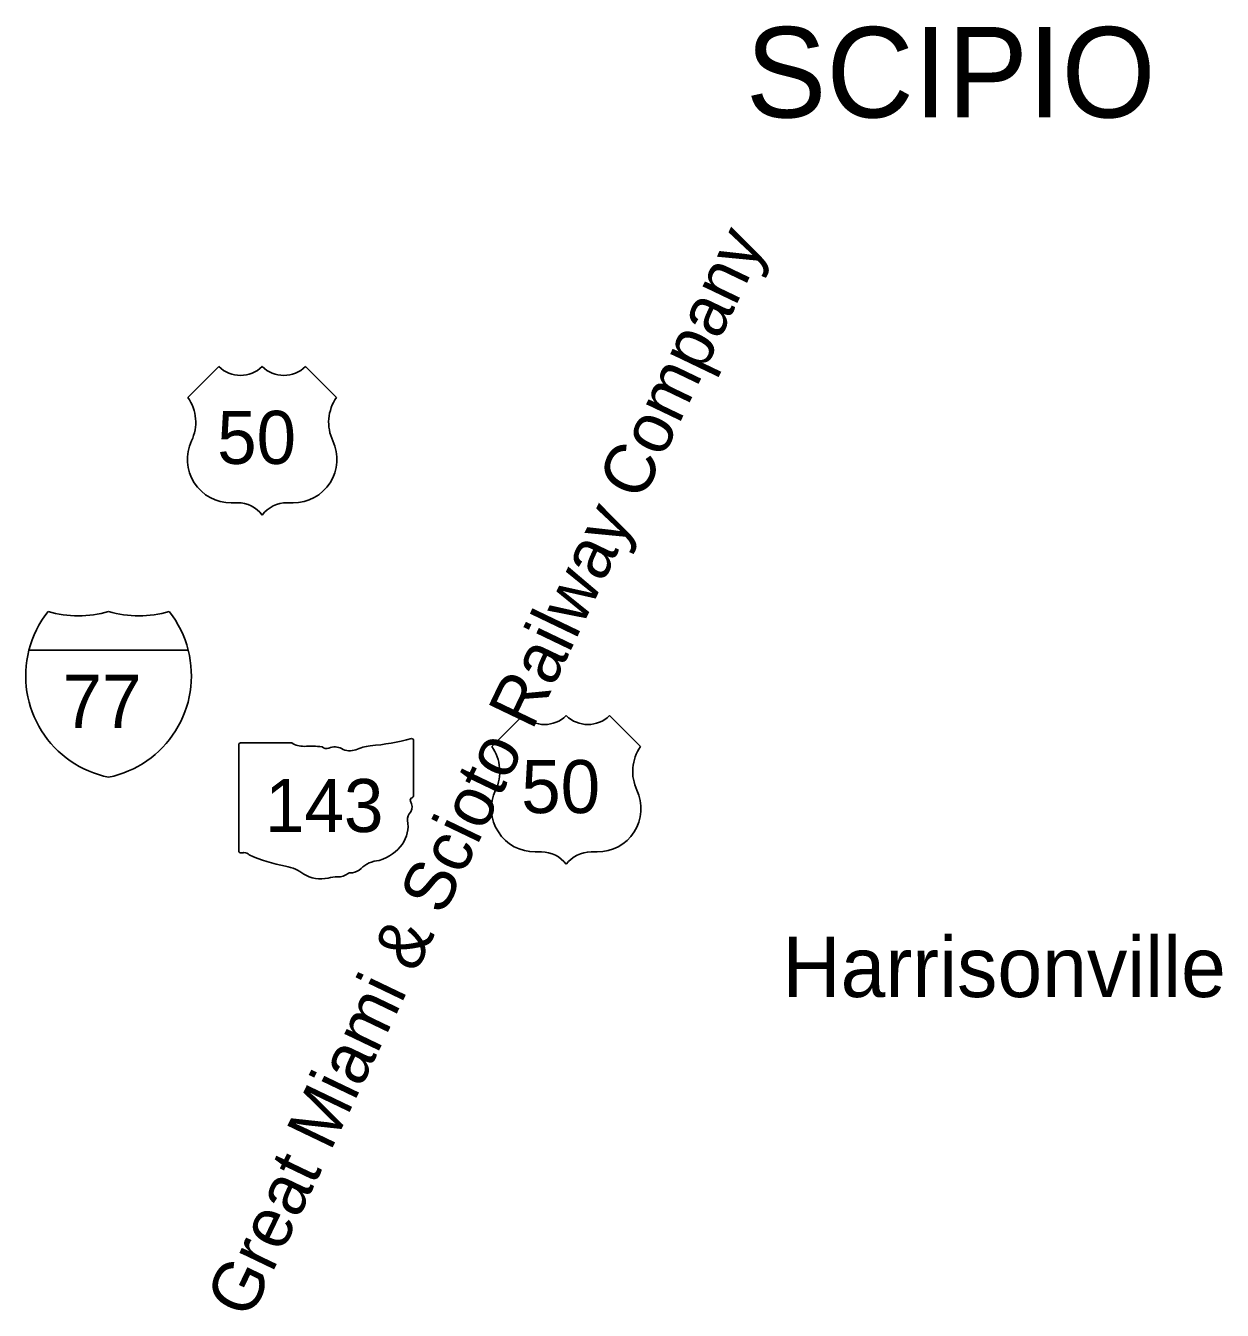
# Model space of a CAD drawing. Extents: x -22 to 431, y -18 to 160.
# Drawn here: x -12.036 to -9.781, y 15.24 to 17.661 of the extents above; entities that cross this region are included whole.
import ezdxf

# ---------------------------------------------------------------- set-up
doc = ezdxf.new("R2010")
doc.units = 0
for name, color, linetype in [('GM_X_Adjacent_County', 7, 'Continuous'), ('GM_X_Airport_Location_Class_2', 7, 'Continuous'), ('GM_X_County_Road_Text', 7, 'Continuous'), ('GM_X_Major_Lake', 7, 'Continuous'), ('GM_X_Rail_Line_Text', 7, 'Continuous'), ('GM_X_Unincorporated_Location', 7, 'Continuous')]:
    doc.layers.add(name, color=color, linetype=linetype)

msp = doc.modelspace()

# ---------------------------------------------------------------- linework, layer by layer
at = {"layer": 'GM_X_Airport_Location_Class_2'}
for p, q in [((-11.6348, 16.3056), (-11.6348, 16.1055)), ((-11.6348, 16.1055), (-11.6348, 16.3056)), ((-11.6348, 16.1055), (-11.6348, 16.3056)), ((-11.6315, 16.3091), (-11.535, 16.3091)), ((-11.3052, 16.314), (-11.3052, 16.2093)), ((-11.3052, 16.2094), (-11.3052, 16.2093))]:
    msp.add_line(p, q, dxfattribs=at)
for centre, major_axis, start_param, end_param in [((-11.631, 16.306), (0.00382, 0), 1.712693, 3.28349), ((-11.512, 16.3323), (0.037, 0), 4.042523, 4.731795), ((-11.4997, 16.1967), (0.133, 0), 1.404758, 1.657858), ((-11.4696, 16.3071), (0.0107, 0), 3.836095, 5.185415), ((-11.4539, 16.2839), (0.0222, 0), 0.950623, 2.079405), ((-11.4252, 16.3157), (0.0267, 0), 4.081561, 5.145723), ((-11.378, 16.2479), (0.0703, 0), 1.699011, 2.107814), ((-11.4226, 16.5819), (0.3495, 0), 4.814394, 5.042369), ((-11.3088, 16.3144), (0.00367, 0), 6.141152, 7.989035), ((-11.306, 16.2016), (0.00568, 0), 1.883978, 3.671073), ((-11.3422, 16.1884), (0.0341, 0), 5.934695, 6.695948), ((-11.3091, 16.2089), (0.00393, 0), 5.05454, 6.418171), ((-11.292, 16.1655), (0.0248, 0), 2.387724, 3.262537), ((-11.403, 16.1522), (0.0874, 0), 5.101752, 6.440018), ((-11.631, 16.1051), (0.00385, 0), 3.00124, 4.508301), ((-11.6304, 16.1255), (0.0294, 0), 4.665946, 4.897461), ((-11.6244, 16.0939), (0.0106, 0), 0.519207, 1.627899), ((-11.4905, 16.2737), (0.2524, 0), 4.195997, 4.488961), ((-11.5658, 16.0156), (0.079, 0), 0.823519, 1.323587), ((-11.3662, 16.0493), (0.0479, 0), 1.647645, 2.488434), ((-11.4804, 16.093), (0.0501, 0), 4.026481, 4.996735), ((-11.4514, 16.0238), (0.0412, 0), 1.495662, 1.94098), ((-11.4478, 16.078), (0.0267, 0), 4.691044, 5.507374), ((-11.4236, 16.0586), (0.00752, 0), 1.147584, 2.315152), ((-11.4268, 16.0861), (0.0282, 0), 4.937069, 5.64225)]:
    msp.add_ellipse(centre, major_axis=major_axis, ratio=0.8, start_param=start_param, end_param=end_param, dxfattribs=at)
at = {"layer": 'GM_X_Rail_Line_Text'}
for p, q in [((-12.0305, 16.4838), (-11.7299, 16.4838)), ((-11.7299, 16.4838), (-12.0305, 16.4838)), ((-11.7299, 16.4838), (-12.0305, 16.4838))]:
    msp.add_line(p, q, dxfattribs=at)
for centre, start, end in [((-11.8411, 16.4359), 141.669, 165.8066), ((-11.9373, 16.7438), 253.0091, 286.9909), ((-11.8231, 16.7438), 253.0091, 286.9909), ((-11.9193, 16.4359), 14.1934, 38.331), ((-11.8411, 16.4359), 165.8066, 258.463), ((-11.9193, 16.4359), 281.537, 14.1934)]:
    msp.add_arc(centre, 0.1953, start, end, dxfattribs=at)
at = {"layer": 'GM_X_Unincorporated_Location'}
for p, q in [((-11.6723, 17.0186), (-11.7307, 16.9603)), ((-11.4506, 16.9603), (-11.5089, 17.0186)), ((-11.649, 16.7618), (-11.6373, 16.7618)), ((-11.5439, 16.7618), (-11.5323, 16.7618)), ((-11.0991, 16.3606), (-11.1575, 16.3022)), ((-10.8773, 16.3022), (-10.9357, 16.3606)), ((-11.0758, 16.1038), (-11.0641, 16.1038)), ((-10.9707, 16.1038), (-10.959, 16.1038))]:
    msp.add_line(p, q, dxfattribs=at)
for centre, radius, start, end in [((-11.6315, 17.0603), 0.0584, 225.573, 314.427), ((-11.5498, 17.0603), 0.0584, 225.573, 314.427), ((-11.7976, 16.9134), 0.0817, 334.5471, 35.0009), ((-11.3836, 16.9134), 0.0817, 144.9991, 205.4529), ((-11.6499, 16.8435), 0.0817, 154.8319, 270.6383), ((-11.5314, 16.8435), 0.0817, 269.3617, 25.1681), ((-11.6373, 16.7035), 0.0584, 36.8699, 90), ((-11.5439, 16.7035), 0.0584, 90, 143.1301), ((-11.0583, 16.4023), 0.0584, 225.573, 314.427), ((-10.9766, 16.4023), 0.0584, 225.573, 314.427), ((-11.2244, 16.2553), 0.0817, 334.5471, 35.0009), ((-10.8104, 16.2553), 0.0817, 144.9991, 205.4529), ((-11.0767, 16.1855), 0.0817, 154.8319, 270.6383), ((-10.9581, 16.1855), 0.0817, 269.3617, 25.1681), ((-11.0641, 16.0454), 0.0584, 36.8699, 90), ((-10.9707, 16.0454), 0.0584, 90, 143.1301)]:
    msp.add_arc(centre, radius, start, end, dxfattribs=at)

# ---------------------------------------------------------------- texts
at = {"layer": 'GM_X_Adjacent_County'}
msp.add_text('Harrisonville', height=0.113636, rotation=0, dxfattribs=at).set_placement((-10.6099, 15.8302))
at = {"layer": 'GM_X_Airport_Location_Class_2'}
for s, p in [('50', (-11.6755, 16.835)), ('77', (-11.9669, 16.3375)), ('50', (-11.1023, 16.1769)), ('143', (-11.5852, 16.1412))]:
    msp.add_text(s, height=0.1, dxfattribs=at).set_placement(p)
at = {"layer": 'GM_X_County_Road_Text'}
msp.add_text('SCIPIO', height=0.17045, rotation=0, dxfattribs=at).set_placement((-10.679, 17.4879))
at = {"layer": 'GM_X_Major_Lake'}
msp.add_text('Great Miami & Scioto Railway Company', height=0.094697, rotation=64.3878, dxfattribs=at).set_placement((-11.6143, 15.2202))

doc.saveas('drawing.dxf')
